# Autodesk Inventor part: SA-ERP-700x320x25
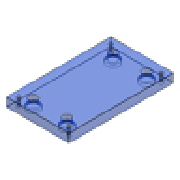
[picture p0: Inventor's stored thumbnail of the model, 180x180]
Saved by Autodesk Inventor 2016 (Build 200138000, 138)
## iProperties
Created: 2015-02
Part Number: SA-ERP-700x320x25
Material: S 55 C
Description: Ejector Retainer Plate
Document SubType Name: Modeling
Designer: Sandeep
Standard Revision: 1
Manufacturer: FUTABA
Language: en-US
Size Designation: 700x320x25
Categories: <MemberInstance><Categories><Category DisplayName="Mold" InternalName="349578f2-f4d4-4954-8c09-8e99297a61c0" Mnemonic="MOLD"><Category DisplayName="Mold Plates"
Density: 7.85 g/cm^3
Appearance: Clear - Blue
IsCustomPart: 1
Author: Sandeep
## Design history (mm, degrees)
sketch "Sketch1"
  geometry: L1 (-160, 350)-(160, 350); L2 (160, 350)-(160, -350); L3 (160, -350)-(-160, -350); L4 (-160, -350)-(-160, 350); 5 further points
  constraints: 8 end point, 2 midpoint, 2 parallel, 1 horizontal, 1 horizontal alignment, 1 perpendicular, 1 vertical alignment
  dimensions: "d84" = 320 distance between parallel lines of L2 L4 (= W_); "d85" = 700 distance between parallel lines of L3 L1 (= L); "d86" = 147 horizontal distance of point (0, 0) point (-147, 337) (= 0.5 x S2_W); "d87" = 337 vertical distance of point (0, 0) point (-147, 337) (= 0.5 x S2_L); "d88" = 128 horizontal distance of point (0, 0) point (-128, 317) (= 0.5 x RP_W); "d89" = 317 vertical distance of point (0, 0) point (-128, 317) (= 0.5 x RP_L)
extrude "Extrusion1" new body sketch "Sketch1" distance "d20" = 25 (= H_); taper "d30" = 0 deg
body "Solid1"
hole "Hole1" sketch "Sketch1" diameter "d90" = 10.106; stored, may be unused: countersink angle "d94" = 90 deg, drill point angle "d96" = 0 deg; dims "d91" = 6, "d92" = 4, "d93" = 2, "d95" = 25 (= H_)
pattern_linear "Rectangular Pattern1" dims "d99" = 674 (computed from S2_L, Nl), "d102" = 294 (computed from S2_W, Nw)
hole "Hole2" sketch "Sketch1" diameter "d103" = 30 (= RP_d1); stored, may be unused: countersink angle "d107" = 90 deg, drill point angle "d109" = 0 deg; dims "d104" = 6, "d105" = 36 (= RP_d2), "d106" = 4 (= RP_k), "d108" = 25 (= H_)
pattern_linear "Rectangular Pattern2" dims "d112" = 634 (computed from RP_L, Nl), "d115" = 256 (computed from RP_W, Nw)
chamfer "Chamfer1" distance "d116" = 0.5; stored, may be unused: second distance "d117" = 2, angle "d118" = 45 deg
other parameters: "L" = 700 [user parameter; used in 1 equation term], "W_" = 320 [user parameter; used in 1 equation term], "H_" = 25 [user parameter; used in 3 equation terms], "S2_W" = 294 [user parameter; used in 2 equation terms], "S2_L" = 674 [user parameter; used in 2 equation terms], "RP_k" = 4 [user parameter; used in 1 equation term], "RP_d1" = 30 [user parameter; used in 1 equation term], "RP_d2" = 36 [user parameter; used in 1 equation term], "RP_L" = 634 [user parameter; used in 2 equation terms], "RP_W" = 256 [user parameter; used in 2 equation terms]
